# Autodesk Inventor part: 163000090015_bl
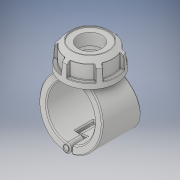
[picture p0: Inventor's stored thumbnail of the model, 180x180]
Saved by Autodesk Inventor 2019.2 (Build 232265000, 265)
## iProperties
Created: 2022-02
Part Number: 163000090015_bl
Material: Generic
Description: Plassadle Threaded 90x1 1/2''
Document SubType Name: Modeling
Designer: comp2
Density: 1 g/cm^3
Appearance: Default
Author: comp2
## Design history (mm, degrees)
derived "16300.ipt"
feature "Solid1::16300.ipt" dims "ScaleForDerivedMember" = 10
feature "Solid2::16300.ipt" dims "ScaleForDerivedMember" = 10
feature "Solid3::16300.ipt" dims "ScaleForDerivedMember" = 10
feature "Solid4::16300.ipt" dims "ScaleForDerivedMember" = 10
tag "TaggingFeature1"
body "Solid1"
body "Solid2"
body "Solid3"
body "Solid4"
other parameters: "d2" = 119 [user parameter], "d3" = 45 [user parameter], "d7" = 113.05 [user parameter], "d8" = 85 deg [user parameter], "d9" = 45 deg [user parameter], "d10" = 102 [user parameter], "d11" = 49 [user parameter], "d12" = 31.2165 [user parameter], "d13" = 42.84 [user parameter], "d14" = 67.2675 [user parameter], "d42" = 2.9 [user parameter], "d49" = 2.38 [user parameter], "d50" = 94 [user parameter], "d51" = 0 [user parameter], "d52" = 20.3 [user parameter], "d53" = 65.45 [user parameter], "d54" = 32.9 [user parameter], "d55" = 0 [user parameter], "d56" = 18.8 [user parameter], "d57" = 18.8 [user parameter], "d59" = 0 [user parameter], "d60" = 94 [user parameter], "d61" = 0 [user parameter], "d62" = 32.9 [user parameter], "d63" = 0 [user parameter], "d65" = 0 [user parameter], "d67" = 0 [user parameter], "d69" = 0 [user parameter], "d70" = 1 [user parameter], "d71" = 90.24 [user parameter], "d72" = 0 [user parameter], "d73" = 2 [user parameter], "d78" = 86.7 [user parameter], "d79" = 5.1 [user parameter], "d80" = 60 deg [user parameter], "d81" = 5.1 [user parameter], "d84" = 0 [user parameter], "d85" = 1 [user parameter], "d87" = 360 deg [user parameter], "d122" = 49 [user parameter], "d124" = 42.80128 [user parameter], "d125" = 2.22975 [user parameter], "d127" = 163 [user parameter], "d129" = 44.845 [user parameter], "d130" = 38.11825 [user parameter], "d131" = 31.85 [user parameter], "d132" = 45 deg [user parameter], "d133" = 22.295 [user parameter], "d134" = 22.4225 [user parameter], "d136" = 0 [user parameter], "d138" = 0 [user parameter], "d1" = 25 [user parameter], "B" = 119 [user parameter], "L" = 94 [user parameter], "E_" = 54 [user parameter], "E1" = 102 [user parameter], "H1" = 163 [user parameter], "H2" = 49 [user parameter], "H3" = 78 [user parameter], "H_costum" = 49 [user parameter], "Rp" = 44.845 [user parameter], "d128" = 44.595 [user parameter]
